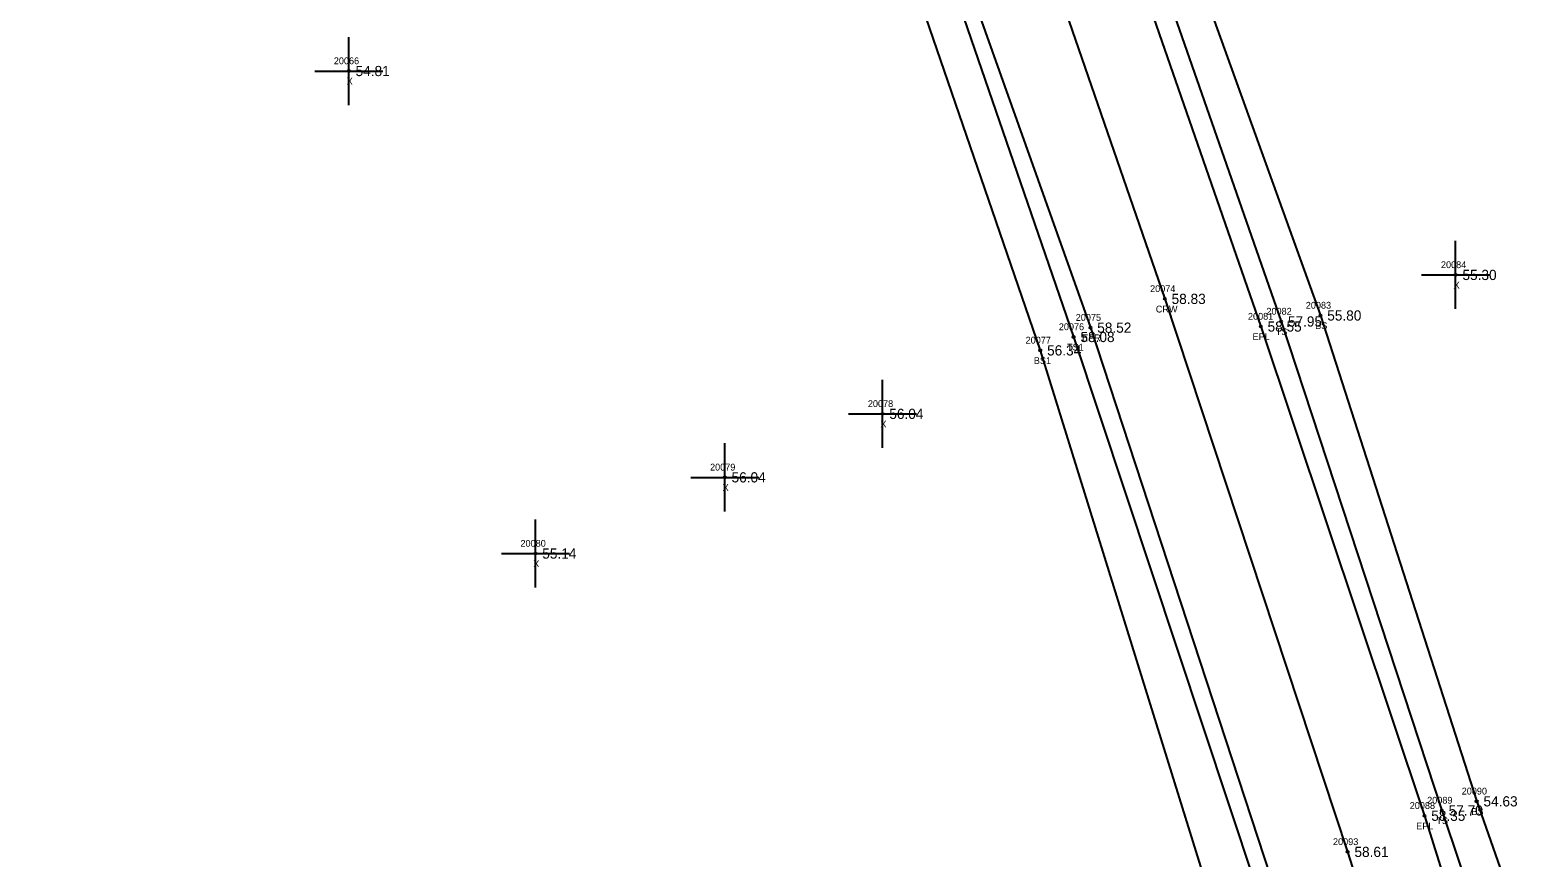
# Model space of a CAD drawing. Extents: x 2396547 to 2397655, y 770185 to 772649.
# Drawn here: x 2396658.8 to 2396880.4, y 772103.6 to 772225.3 of the extents above; entities that cross this region are included whole.
import ezdxf

# ---------------------------------------------------------------- set-up
doc = ezdxf.new("R2010")
doc.units = 0
for name, color, linetype in [('RD_DTM_BkLn1', 7, 'Continuous'), ('RD_DTM_BkLn2', 7, 'Continuous'), ('RD_DTM_BkLn_txCode', 7, 'Continuous'), ('RD_EX_Misc', 7, 'Continuous'), ('RD_EX_Misc_txCode', 7, 'Continuous'), ('RD_EX_Road', 7, 'Continuous'), ('RD_EX_Road_txCode', 7, 'Continuous'), ('RD_EX_TX_Misc_ELEV', 7, 'Continuous'), ('RD_EX_TX_Road_ELEV', 7, 'Continuous'), ('RD_HC_Survey_ELEV', 7, 'Continuous'), ('RD_HC_Survey_txCode', 7, 'Continuous'), ('RD_SMD_Locator', 7, 'Continuous')]:
    doc.layers.add(name, color=color, linetype=linetype)

msp = doc.modelspace()

# ---------------------------------------------------------------- linework, layer by layer
at = {"layer": 'RD_DTM_BkLn1'}
msp.add_lwpolyline([(2396669.86, 772614.94), (2396704.28, 772521.49), (2396739.29, 772426.89), (2396775.36, 772328.69), (2396800.21, 772259.35), (2396825.58, 772185.8), (2396852.46, 772104.52), (2396872.48, 772041.55), (2396897.57, 771959.72), (2396918.76, 771888.68), (2396939.09, 771818.34), (2396959.29, 771747.62), (2396993.72, 771617.68), (2397022.56, 771506.67), (2397049.1, 771404.69)], dxfattribs=at)
at = {"layer": 'RD_DTM_BkLn2'}
for points in [[(2396760.04, 772432.43), (2396789.87, 772348.56), (2396819.19, 772264.69), (2396848.46, 772183.36), (2396871.43, 772111.95), (2396893.38, 772049.37), (2396898.43, 772032.73), (2396909.27, 772037.73)], [(2396760.04, 772432.43), (2396760.2, 772413.09), (2396784.34, 772347.64), (2396814.22, 772264.11), (2396842.68, 772182.48), (2396866.31, 772110.61), (2396887.53, 772047.36), (2396893.79, 772029.88), (2396898.47, 772029.01), (2396909.27, 772037.73)], [(2396786.67, 772254.3), (2396812.18, 772180.2), (2396838.8, 772099.9), (2396858.54, 772037.17), (2396883.18, 771955.21), (2396904.21, 771884.05), (2396902.37, 771874.08)], [(2396781.71, 772252.52), (2396807.28, 772178.23), (2396832.42, 772097.31), (2396850.69, 772038.97), (2396852.44, 772035.31), (2396852.26, 772031.59), (2396879.38, 771953.92), (2396900.31, 771883.04), (2396902.37, 771874.08)]]:
    msp.add_lwpolyline(points, dxfattribs=at)
at = {"layer": 'RD_EX_Misc'}
for p, q in [((2396705.62, 772214.29), (2396705.62, 772224.29)), ((2396700.62, 772219.29), (2396710.62, 772219.29)), ((2396868.34, 772184.32), (2396868.34, 772194.32)), ((2396863.34, 772189.32), (2396873.34, 772189.32)), ((2396784.08, 772163.9), (2396784.08, 772173.9)), ((2396779.08, 772168.9), (2396789.08, 772168.9)), ((2396760.89, 772154.57), (2396760.89, 772164.57)), ((2396755.89, 772159.57), (2396765.89, 772159.57)), ((2396733.06, 772143.37), (2396733.06, 772153.37)), ((2396728.06, 772148.37), (2396738.06, 772148.37))]:
    msp.add_line(p, q, dxfattribs=at)
at = {"layer": 'RD_EX_Road'}
for points in [[(2396680.92, 772617.84), (2396715.6, 772525.73), (2396750.68, 772430.62), (2396786.3, 772332.21), (2396811.38, 772263.31), (2396839.69, 772181.74), (2396863.75, 772109.83), (2396883.63, 772046.56), (2396889.54, 772027.11), (2396896.25, 772004.37), (2396904.34, 771978.33), (2396908.24, 771964.89), (2396921.74, 771919.68), (2396927.03, 771902.11), (2396950.2, 771821.74), (2396970.47, 771750.68), (2396978.33, 771721.29), (2396990.58, 771675.04), (2397004.94, 771620.49), (2397034.26, 771508.8), (2397061.11, 771410.49), (2397060.64, 771407.04), (2397062.07, 771407.67)], [(2396658.78, 772611.07), (2396693.37, 772516.9), (2396729.65, 772418.78), (2396760.7, 772333.11), (2396788.58, 772254.87), (2396814.65, 772181.57), (2396841.1, 772100.86), (2396861.19, 772037.76), (2396886.09, 771955.71), (2396907.15, 771884.49), (2396928.56, 771811.72), (2396947.65, 771744.09), (2396985.17, 771602.64), (2397011.11, 771504.04), (2397037.95, 771404.25), (2397039, 771401.22)]]:
    msp.add_lwpolyline(points, dxfattribs=at)
at = {"layer": 'RD_SMD_Locator'}
for centre in [(2396705.62, 772219.29), (2396868.34, 772189.32), (2396825.58, 772185.8), (2396842.68, 772182.48), (2396848.46, 772183.36), (2396812.18, 772180.2), (2396814.65, 772181.57), (2396839.69, 772181.74), (2396807.28, 772178.23), (2396784.08, 772168.9), (2396760.89, 772159.57), (2396733.06, 772148.37), (2396871.43, 772111.95), (2396863.75, 772109.83), (2396866.31, 772110.61), (2396852.46, 772104.52)]:
    msp.add_circle(centre, 0.15, dxfattribs=at)

# ---------------------------------------------------------------- texts
at = {"layer": 'RD_DTM_BkLn_txCode'}
for s, p in [('20082', (2396840.52, 772183.48)), ('20083', (2396846.31, 772184.36)), ('20076', (2396810, 772181.2)), ('BS', (2396847.69, 772181.36)), ('20077', (2396805.12, 772179.23)), ('TS', (2396841.89, 772180.48)), ('TS1', (2396811.22, 772178.2)), ('BS1', (2396806.33, 772176.23)), ('20090', (2396869.23, 772112.95)), ('20089', (2396864.15, 772111.61)), ('TS', (2396865.51, 772108.61)), ('BS', (2396870.65, 772109.95))]:
    msp.add_text(s, height=1, dxfattribs=at).set_placement(p)
at = {"layer": 'RD_EX_Misc_txCode'}
for s, p in [('20066', (2396703.42, 772220.29)), ('X', (2396705.31, 772217.29)), ('20084', (2396866.18, 772190.32)), ('X', (2396868.03, 772187.32)), ('20078', (2396781.93, 772169.9)), ('X', (2396783.77, 772166.9)), ('20079', (2396758.73, 772160.57)), ('X', (2396760.58, 772157.57)), ('20080', (2396730.86, 772149.37)), ('X', (2396732.74, 772146.37))]:
    msp.add_text(s, height=1, dxfattribs=at).set_placement(p)
at = {"layer": 'RD_EX_Road_txCode'}
for s, p in [('20075', (2396812.49, 772182.57)), ('20081', (2396837.81, 772182.74)), ('EPR', (2396813.42, 772179.57)), ('EPL', (2396838.48, 772179.74)), ('20088', (2396861.59, 772110.83)), ('EPL', (2396862.54, 772107.83))]:
    msp.add_text(s, height=1, dxfattribs=at).set_placement(p)
at = {"layer": 'RD_EX_TX_Misc_ELEV'}
for s, p in [('54.81', (2396706.62, 772218.54)), ('55.30', (2396869.34, 772188.57)), ('57.95', (2396843.68, 772181.73)), ('55.80', (2396849.46, 772182.61)), ('58.08', (2396813.18, 772179.45)), ('56.34', (2396808.28, 772177.48)), ('56.04', (2396785.08, 772168.15)), ('56.04', (2396761.89, 772158.82)), ('55.14', (2396734.06, 772147.62)), ('57.70', (2396867.31, 772109.86)), ('54.63', (2396872.43, 772111.2))]:
    msp.add_text(s, height=1.5, dxfattribs=at).set_placement(p)
at = {"layer": 'RD_EX_TX_Road_ELEV'}
for s, p in [('58.52', (2396815.65, 772180.82)), ('58.55', (2396840.69, 772180.99)), ('58.35', (2396864.75, 772109.08))]:
    msp.add_text(s, height=1.5, dxfattribs=at).set_placement(p)
at = {"layer": 'RD_HC_Survey_ELEV'}
for s, p in [('58.83', (2396826.58, 772185.05)), ('58.61', (2396853.46, 772103.77))]:
    msp.add_text(s, height=1.5, dxfattribs=at).set_placement(p)
at = {"layer": 'RD_HC_Survey_txCode'}
for s, p in [('20074', (2396823.42, 772186.8)), ('CRW', (2396824.26, 772183.8)), ('20093', (2396850.31, 772105.52))]:
    msp.add_text(s, height=1, dxfattribs=at).set_placement(p)

doc.saveas('drawing.dxf')
